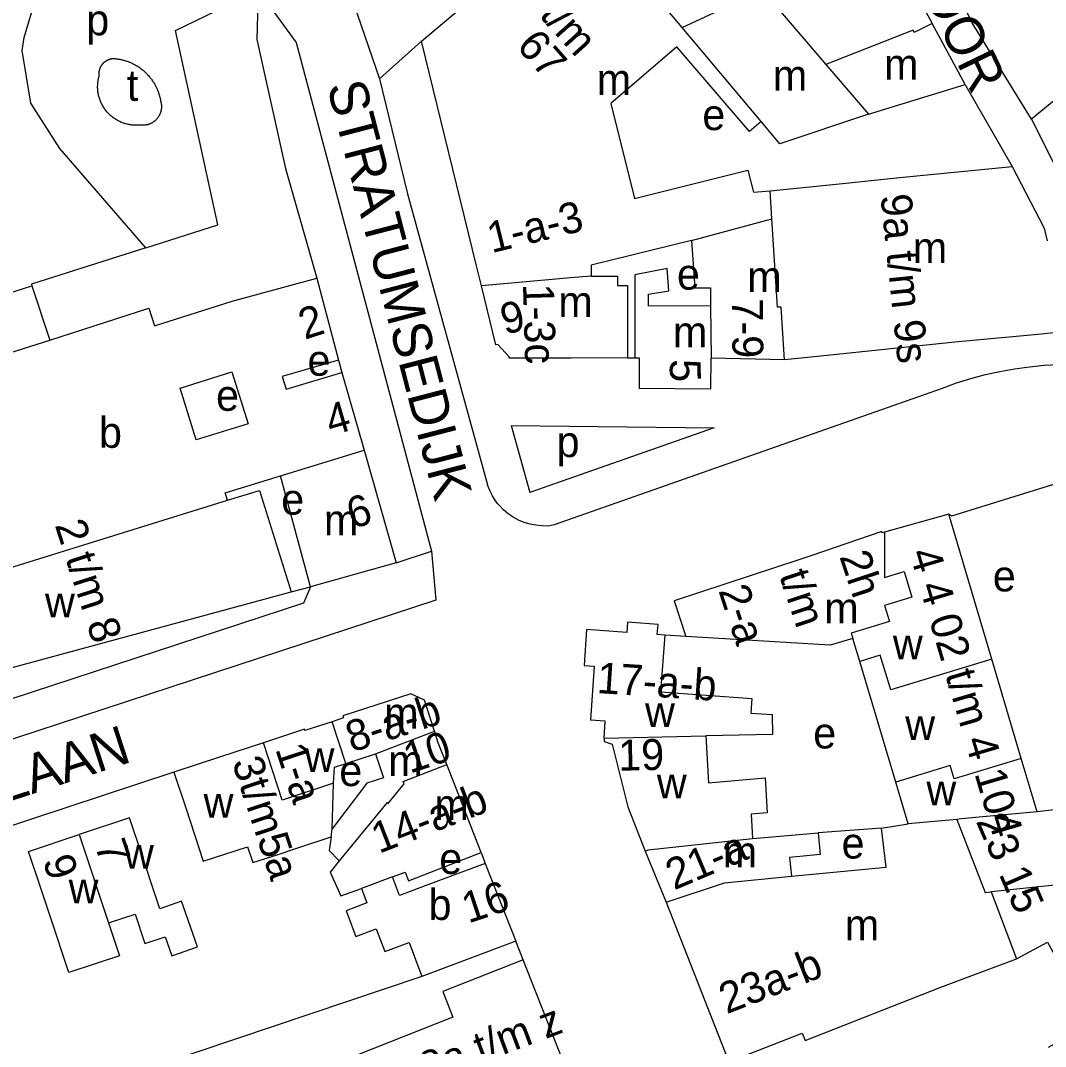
# Model space of a CAD drawing. Extents: x 160673 to 161924, y 382258 to 384145.
# Drawn here: x 161653.4 to 161785.9, y 382756.1 to 382888.8 of the extents above; entities that cross this region are included whole.
import ezdxf

# ---------------------------------------------------------------- set-up
doc = ezdxf.new("R2010")
doc.units = 0
for name, color, linetype in [('BLT_Basislijn', 7, 'Continuous'), ('BLT_Bebouwing', 7, 'Continuous'), ('BLT_Centroide', 7, 'Continuous'), ('BLT_Huisnummer', 7, 'Continuous'), ('BLT_Huisnummer_reeks', 7, 'Continuous'), ('BLT_Onderdoorgang_en_onderverdeling', 7, 'Continuous'), ('BLT_Onderverdeling_panden', 7, 'Continuous'), ('BLT_Straatnaam', 7, 'Continuous')]:
    doc.layers.add(name, color=color, linetype=linetype)

msp = doc.modelspace()

# ---------------------------------------------------------------- linework, layer by layer
at = {"layer": 'BLT_Basislijn'}
for p, q in [((161696.46, 382891.05), (161699.83, 382881.27)), ((161699.83, 382881.27), (161705.26, 382886.11)), ((161775.81, 382880.04), (161781.64, 382869.92)), ((161687.67, 382869.67), (161691.73, 382855.47)), ((161731.89, 382845.15), (161732.86, 382845.18)), ((161694.52, 382844.86), (161694.96, 382843.25)), ((161771.86, 382840.94), (161722.4, 382823.55)), ((161722.4, 382823.55), (161721.64, 382823.38)), ((161701.98, 382818.64), (161706.56, 382820.15)), ((161688.4, 382814.89), (161690.9, 382815.57)), ((161739.44, 382809.11), (161736.71, 382809.3)), ((161764.74, 382784.33), (161756.57, 382783.73)), ((161712.96, 382781.19), (161713.49, 382779.79)), ((161718.38, 382767.32), (161717.44, 382769.71))]:
    msp.add_line(p, q, dxfattribs=at)
for points in [[(161784.14, 382876.02), (161776.46, 382888.51), (161772.05, 382897.69), (161770.77, 382900), (161757.99, 382926.38), (161756.93, 382927.5), (161750.63, 382931.05)], [(161669.6, 382859.39), (161658.47, 382872.25), (161654.74, 382878.09), (161653.59, 382884.93), (161653.85, 382886.6), (161655.45, 382891.97), (161655.94, 382893.21), (161660.68, 382894.52), (161664.2, 382895.29), (161667.2, 382896.2), (161670.19, 382897.12), (161675.06, 382898.91), (161679.92, 382900.69)], [(161762.41, 382899.43), (161763.63, 382900), (161764.76, 382900.57), (161765.06, 382900), (161771.29, 382888.41)], [(161669.6, 382859.39), (161678.93, 382862.35), (161673.43, 382887.52), (161684.14, 382892.71)], [(161684.14, 382892.71), (161683.96, 382886.35), (161687.67, 382869.67)], [(161684.14, 382892.71), (161689.03, 382885.93), (161706.56, 382820.15)], [(161663.57, 382881.66), (161663.57, 382881.69), (161663.56, 382881.73), (161663.56, 382881.77), (161663.56, 382881.8), (161663.56, 382881.84), (161663.56, 382881.88), (161663.56, 382881.92), (161663.56, 382881.96), (161663.56, 382882), (161663.56, 382882.03), (161663.56, 382882.07), (161663.57, 382882.11), (161663.57, 382882.15), (161663.58, 382882.19), (161663.58, 382882.23), (161663.59, 382882.27), (161663.6, 382882.31), (161663.61, 382882.35), (161663.62, 382882.39), (161663.63, 382882.43), (161663.64, 382882.47), (161663.65, 382882.51), (161663.66, 382882.55), (161663.68, 382882.59), (161663.69, 382882.63), (161663.71, 382882.67), (161663.72, 382882.7), (161663.74, 382882.74), (161663.76, 382882.78), (161663.78, 382882.82), (161663.8, 382882.86), (161663.82, 382882.89), (161663.84, 382882.93), (161663.86, 382882.97), (161663.89, 382883), (161663.91, 382883.04), (161663.94, 382883.07), (161663.96, 382883.11), (161663.99, 382883.14), (161664.01, 382883.18), (161664.04, 382883.21), (161664.07, 382883.24), (161664.1, 382883.27), (161664.13, 382883.3), (161664.16, 382883.33), (161664.19, 382883.36), (161664.22, 382883.39), (161664.26, 382883.42), (161664.29, 382883.45), (161664.32, 382883.47), (161664.36, 382883.5), (161664.39, 382883.52), (161664.42, 382883.55), (161664.46, 382883.57), (161664.5, 382883.59), (161664.53, 382883.61), (161664.57, 382883.63), (161664.6, 382883.65), (161664.64, 382883.67), (161664.68, 382883.69), (161664.71, 382883.71), (161664.75, 382883.72), (161664.79, 382883.74), (161664.83, 382883.75), (161664.86, 382883.77), (161664.9, 382883.78), (161664.94, 382883.79), (161664.98, 382883.81), (161665.01, 382883.82), (161665.05, 382883.83), (161665.09, 382883.83), (161665.13, 382883.84), (161665.16, 382883.85), (161665.2, 382883.86), (161665.24, 382883.86), (161665.28, 382883.87), (161665.31, 382883.87), (161665.35, 382883.88), (161665.39, 382883.88)], [(161665.39, 382883.88), (161665.49, 382883.87), (161665.59, 382883.86), (161665.7, 382883.85), (161665.81, 382883.84), (161665.91, 382883.83), (161666.02, 382883.81), (161666.13, 382883.79), (161666.23, 382883.78), (161666.34, 382883.75), (161666.45, 382883.73), (161666.55, 382883.71), (161666.66, 382883.68), (161666.77, 382883.65), (161666.88, 382883.62), (161666.98, 382883.59), (161667.09, 382883.55), (161667.2, 382883.52), (161667.3, 382883.48), (161667.41, 382883.44), (161667.51, 382883.4), (161667.62, 382883.35), (161667.72, 382883.31), (161667.83, 382883.26), (161667.93, 382883.21), (161668.03, 382883.16), (161668.14, 382883.1), (161668.24, 382883.05), (161668.34, 382882.99), (161668.44, 382882.93), (161668.54, 382882.87), (161668.64, 382882.8), (161668.73, 382882.74), (161668.83, 382882.67), (161668.92, 382882.6), (161669.02, 382882.53), (161669.11, 382882.46), (161669.2, 382882.39), (161669.29, 382882.31), (161669.38, 382882.24), (161669.47, 382882.16), (161669.55, 382882.08), (161669.64, 382882), (161669.72, 382881.91), (161669.8, 382881.83), (161669.88, 382881.74), (161669.96, 382881.66), (161670.04, 382881.57), (161670.11, 382881.48), (161670.18, 382881.39), (161670.26, 382881.29), (161670.33, 382881.2), (161670.39, 382881.11), (161670.46, 382881.01), (161670.52, 382880.92), (161670.59, 382880.82), (161670.65, 382880.72), (161670.71, 382880.62), (161670.76, 382880.52), (161670.82, 382880.42), (161670.87, 382880.32), (161670.92, 382880.22), (161670.97, 382880.12), (161671.02, 382880.02), (161671.06, 382879.91), (161671.11, 382879.81), (161671.15, 382879.71), (161671.19, 382879.6), (161671.23, 382879.5), (161671.26, 382879.4), (161671.3, 382879.29), (161671.33, 382879.19), (161671.36, 382879.08), (161671.39, 382878.98), (161671.42, 382878.88), (161671.44, 382878.77), (161671.46, 382878.67), (161671.48, 382878.56), (161671.5, 382878.46), (161671.52, 382878.36)], [(161668.89, 382875.26), (161668.78, 382875.25), (161668.67, 382875.24), (161668.57, 382875.24), (161668.46, 382875.24), (161668.35, 382875.24), (161668.23, 382875.24), (161668.12, 382875.24), (161668.01, 382875.25), (161667.89, 382875.26), (161667.78, 382875.27), (161667.66, 382875.29), (161667.55, 382875.3), (161667.43, 382875.33), (161667.31, 382875.35), (161667.19, 382875.38), (161667.07, 382875.41), (161666.95, 382875.44), (161666.84, 382875.48), (161666.72, 382875.52), (161666.6, 382875.56), (161666.48, 382875.61), (161666.36, 382875.66), (161666.25, 382875.71), (161666.13, 382875.77), (161666.02, 382875.83), (161665.9, 382875.89), (161665.79, 382875.96), (161665.68, 382876.03), (161665.57, 382876.1), (161665.46, 382876.17), (161665.35, 382876.25), (161665.24, 382876.34), (161665.14, 382876.42), (161665.04, 382876.51), (161664.94, 382876.6), (161664.84, 382876.69), (161664.75, 382876.79), (161664.66, 382876.89), (161664.57, 382876.99), (161664.48, 382877.09), (161664.4, 382877.2), (161664.32, 382877.31), (161664.24, 382877.42), (161664.17, 382877.53), (161664.1, 382877.65), (161664.03, 382877.76), (161663.96, 382877.88), (161663.9, 382878), (161663.84, 382878.12), (161663.79, 382878.24), (161663.74, 382878.36), (161663.69, 382878.48), (161663.65, 382878.61), (161663.6, 382878.73), (161663.57, 382878.86), (161663.53, 382878.98), (161663.5, 382879.1), (161663.48, 382879.23), (161663.45, 382879.35), (161663.43, 382879.48), (161663.41, 382879.6), (161663.4, 382879.73), (161663.39, 382879.85), (161663.38, 382879.97), (161663.37, 382880.09), (161663.37, 382880.21), (161663.37, 382880.33), (161663.38, 382880.45), (161663.38, 382880.57), (161663.39, 382880.68), (161663.4, 382880.8), (161663.42, 382880.91), (161663.43, 382881.02), (161663.45, 382881.13), (161663.47, 382881.24), (161663.5, 382881.35), (161663.52, 382881.45), (161663.55, 382881.55), (161663.57, 382881.66)], [(161699.83, 382881.27), (161703.43, 382866.39), (161713.79, 382828.76)], [(161775.55, 382880.5), (161775.65, 382880.33), (161775.81, 382880.04)], [(161671.52, 382878.36), (161671.54, 382878.31), (161671.55, 382878.26), (161671.56, 382878.21), (161671.57, 382878.15), (161671.58, 382878.1), (161671.59, 382878.05), (161671.6, 382877.99), (161671.61, 382877.94), (161671.61, 382877.88), (161671.62, 382877.82), (161671.62, 382877.77), (161671.62, 382877.71), (161671.62, 382877.65), (161671.62, 382877.59), (161671.62, 382877.53), (161671.62, 382877.47), (161671.61, 382877.41), (161671.6, 382877.35), (161671.6, 382877.29), (161671.59, 382877.23), (161671.57, 382877.17), (161671.56, 382877.1), (161671.54, 382877.04), (161671.53, 382876.98), (161671.51, 382876.92), (161671.49, 382876.86), (161671.47, 382876.8), (161671.44, 382876.74), (161671.42, 382876.68), (161671.39, 382876.62), (161671.36, 382876.56), (161671.33, 382876.5), (161671.3, 382876.44), (161671.26, 382876.39), (161671.23, 382876.33), (161671.19, 382876.28), (161671.15, 382876.22), (161671.11, 382876.17), (161671.07, 382876.12), (161671.02, 382876.07), (161670.98, 382876.02), (161670.93, 382875.97), (161670.89, 382875.92), (161670.84, 382875.88), (161670.79, 382875.83), (161670.74, 382875.79), (161670.69, 382875.75), (161670.63, 382875.71), (161670.58, 382875.67), (161670.53, 382875.63), (161670.47, 382875.6), (161670.42, 382875.57), (161670.36, 382875.53), (161670.3, 382875.5), (161670.24, 382875.48), (161670.19, 382875.45), (161670.13, 382875.42), (161670.07, 382875.4), (161670.01, 382875.38), (161669.95, 382875.36), (161669.89, 382875.34), (161669.84, 382875.32), (161669.78, 382875.31), (161669.72, 382875.3), (161669.66, 382875.28), (161669.6, 382875.27), (161669.54, 382875.26), (161669.49, 382875.26), (161669.43, 382875.25), (161669.37, 382875.25), (161669.32, 382875.24), (161669.26, 382875.24), (161669.2, 382875.24), (161669.15, 382875.24), (161669.1, 382875.24), (161669.04, 382875.25), (161668.99, 382875.25), (161668.94, 382875.26), (161668.89, 382875.26)], [(161669.6, 382859.39), (161654.81, 382854.69), (161654.88, 382854.49)], [(161644.34, 382843.41), (161642.05, 382850.53), (161641.85, 382851.77), (161641.96, 382853.02), (161642.37, 382854.21), (161643.08, 382855.25), (161644.05, 382856.05), (161645.15, 382856.66), (161646.38, 382856.92), (161647.64, 382856.88), (161649.02, 382856.46), (161650.05, 382855.84), (161650.9, 382854.98), (161651.64, 382853.46), (161654.88, 382854.49)], [(161654.88, 382854.49), (161657.17, 382847.46)], [(161793.56, 382844.1), (161791.63, 382844.24), (161789.68, 382844.29), (161787.74, 382844.27), (161785.8, 382844.16), (161783.87, 382843.98), (161781.95, 382843.71), (161780.04, 382843.37), (161778.14, 382842.95), (161776.26, 382842.45), (161774.41, 382841.88), (161772.58, 382841.22), (161771.86, 382840.94)], [(161716.87, 382836.41), (161719.26, 382827.74)], [(161716.87, 382836.41), (161743.1, 382836.13)], [(161743.1, 382836.13), (161719.26, 382827.74)], [(161715.14, 382826.3), (161714.84, 382826.67), (161714.42, 382827.33), (161714.07, 382828.03), (161713.79, 382828.76)], [(161773.44, 382824.94), (161773.84, 382824.74), (161787.59, 382828.98)], [(161721.64, 382823.38), (161720.84, 382823.44), (161720.06, 382823.51), (161719.29, 382823.66), (161718.54, 382823.88), (161717.81, 382824.18), (161717.12, 382824.55), (161716.48, 382824.99), (161715.87, 382825.49), (161715.33, 382826.05), (161715.14, 382826.3)], [(161706.56, 382820.15), (161707.11, 382813.82), (161604.11, 382780.01)], [(161690.9, 382815.57), (161690, 382813.46), (161638.43, 382796.53)], [(161673.24, 382791.58), (161599.67, 382767.3), (161594.58, 382765.48), (161592.95, 382764.43), (161588.72, 382761.07), (161582.73, 382756.8), (161576.92, 382752.34), (161575.39, 382751.38), (161572.83, 382749.04)], [(161705.29, 382765.14), (161671.57, 382753.82), (161672.26, 382751.88), (161666.99, 382750.02), (161666.19, 382749.74), (161666.83, 382747.94), (161647.7, 382741.2)]]:
    msp.add_lwpolyline(points, dxfattribs=at)
at = {"layer": 'BLT_Bebouwing'}
for p, q in [((161809.67, 382897.12), (161784.14, 382876.02)), ((161749.33, 382892.73), (161757.56, 382883.09)), ((161775.55, 382880.5), (161771.29, 382888.41)), ((161763.07, 382876.66), (161775.55, 382880.5)), ((161767.1, 382868.47), (161781.64, 382869.92)), ((161750.34, 382866.78), (161758.44, 382867.6)), ((161758.44, 382867.6), (161767.1, 382868.47)), ((161750.57, 382863.13), (161750.34, 382866.78)), ((161740.19, 382860.32), (161750.57, 382863.13)), ((161713.01, 382854.49), (161712.38, 382857.06)), ((161691.73, 382855.47), (161694.52, 382844.86)), ((161784.52, 382848.14), (161774.64, 382847.22)), ((161787.52, 382848.44), (161784.52, 382848.14)), ((161724.63, 382845.14), (161717.66, 382845.13)), ((161731.89, 382845.15), (161724.63, 382845.14)), ((161752.2, 382844.92), (161742.7, 382845.12)), ((161694.52, 382844.86), (161687.25, 382842.74)), ((161694.96, 382843.25), (161697.83, 382833.21)), ((161697.83, 382833.21), (161701.98, 382818.64)), ((161690.9, 382815.57), (161687, 382829.89)), ((161773.44, 382824.94), (161765.15, 382822.62)), ((161779.01, 382806.18), (161773.44, 382824.94)), ((161701.98, 382818.64), (161690.9, 382815.57)), ((161754.32, 382819.13), (161737.91, 382813.73)), ((161755.62, 382819.57), (161754.32, 382819.13)), ((161635.19, 382800.49), (161688.4, 382814.89)), ((161737.91, 382813.73), (161739.44, 382809.11)), ((161761.93, 382805.9), (161761.04, 382808.89)), ((161766.59, 382790.3), (161761.93, 382805.9)), ((161782.81, 382793.37), (161779.01, 382806.18)), ((161688.06, 382796.45), (161684.81, 382795.38)), ((161684.81, 382795.38), (161679.14, 382793.52)), ((161679.14, 382793.52), (161673.24, 382791.58)), ((161784.86, 382786.47), (161782.81, 382793.37)), ((161712.96, 382781.19), (161708.53, 382792.58)), ((161768.2, 382784.89), (161766.59, 382790.3)), ((161764.74, 382784.33), (161768.2, 382784.89)), ((161734.2, 382781.37), (161736.91, 382774.75)), ((161701.51, 382778.05), (161703.14, 382778.65)), ((161713.49, 382779.79), (161717.44, 382769.71)), ((161736.91, 382774.75), (161745, 382754.12)), ((161717.44, 382769.71), (161705.29, 382765.14)), ((161724.12, 382752.78), (161718.38, 382767.32))]:
    msp.add_line(p, q, dxfattribs=at)
for points in [[(161712.38, 382857.06), (161705.26, 382886.11), (161725.82, 382903.46)], [(161771.29, 382888.41), (161768.96, 382887.22), (161768.84, 382887.53), (161757.56, 382883.09)], [(161738.29, 382885.39), (161729.72, 382878.05), (161732.78, 382865.78)], [(161749.17, 382875.71), (161747.67, 382874.42), (161738.29, 382885.39)], [(161763.07, 382876.66), (161751.61, 382872.86), (161749.17, 382875.71)], [(161784.14, 382876.02), (161789.67, 382865.07), (161791.04, 382860.71)], [(161732.78, 382865.78), (161747.47, 382869.44), (161748.19, 382866.58), (161750.34, 382866.78)], [(161781.64, 382869.92), (161785.8, 382861.92), (161786.16, 382860.28)], [(161740.19, 382860.32), (161727.19, 382857.14), (161727.19, 382855.74)], [(161740.19, 382860.32), (161740.62, 382854.2), (161742.61, 382854.2), (161742.63, 382851.88)], [(161727.19, 382855.74), (161730.58, 382855.74), (161730.58, 382854.51), (161731.89, 382854.51), (161731.89, 382850.15), (161731.89, 382845.15)], [(161742.63, 382851.88), (161734.63, 382851.87), (161734.63, 382853.4), (161737.26, 382853.85), (161737.04, 382856.74), (161732.85, 382855.91), (161732.85, 382850.11), (161732.86, 382845.18)], [(161670.73, 382849.29), (161680.77, 382852.48), (161691.73, 382855.47)], [(161717.66, 382845.13), (161716.61, 382845.13), (161716.61, 382845.3), (161715.11, 382846.91), (161714.88, 382846.86), (161713.01, 382854.49)], [(161657.17, 382847.46), (161669.99, 382851.6), (161670.73, 382849.29)], [(161644.34, 382843.41), (161657.17, 382847.46)], [(161774.64, 382847.22), (161755.22, 382845.22), (161752.2, 382844.92)], [(161732.86, 382845.18), (161733.41, 382845.17), (161733.41, 382841.24), (161742.66, 382841.14), (161742.7, 382845.12)], [(161687.25, 382842.74), (161687.73, 382841.12), (161694.96, 382843.25)], [(161680.18, 382826.76), (161679.88, 382827.71), (161687, 382829.89)], [(161680.18, 382826.76), (161684.3, 382828.03), (161688.4, 382814.89)], [(161765.15, 382822.62), (161764.84, 382822.53), (161764.78, 382822.71), (161755.62, 382819.57)], [(161736.71, 382809.3), (161735.74, 382809.37), (161735.84, 382810.69), (161731.89, 382810.98), (161731.79, 382809.66), (161726.61, 382810.04)], [(161726.61, 382810.04), (161726.27, 382805.37), (161727.6, 382805.27), (161727.12, 382798.29)], [(161736.71, 382809.3), (161736.17, 382801.98), (161747.98, 382801.12), (161747.84, 382799.23), (161750.61, 382799.03), (161750.64, 382796.44), (161742.02, 382796.29)], [(161761.04, 382808.89), (161758.1, 382808.01), (161739.44, 382809.11)], [(161703.86, 382801.71), (161695.1, 382798.86), (161695.18, 382798.59), (161693.7, 382798.11)], [(161706.94, 382796.89), (161705.62, 382800.91), (161703.86, 382801.71)], [(161693.7, 382798.11), (161690.18, 382796.95), (161690.13, 382797.13), (161688.06, 382796.45)], [(161728.89, 382795.99), (161728.99, 382798.18), (161727.12, 382798.29)], [(161708.53, 382792.58), (161707.43, 382795.39), (161706.94, 382796.89)], [(161728.89, 382795.99), (161728.87, 382795.53), (161729.92, 382795.22), (161731.94, 382787.1)], [(161742.02, 382796.29), (161742.36, 382790.22), (161749.68, 382790.86), (161749.94, 382786.32), (161747.87, 382786.14), (161748.04, 382783.01)], [(161699.31, 382793.96), (161700.33, 382790.85), (161698.18, 382790.14), (161693.69, 382784.25)], [(161695.48, 382792.7), (161699.31, 382793.96)], [(161693.88, 382790.18), (161694.02, 382792.22), (161695.48, 382792.7)], [(161673.24, 382791.58), (161674.8, 382786.83), (161677.03, 382780.06), (161682.76, 382781.94)], [(161693.69, 382784.25), (161693.88, 382790.13), (161693.88, 382790.18)], [(161797.5, 382787.92), (161784.86, 382786.47)], [(161731.94, 382787.1), (161734.2, 382781.37)], [(161671.42, 382773.92), (161670.99, 382775.21), (161669.09, 382780.93), (161667.51, 382785.67), (161660.98, 382783.5)], [(161753.1, 382778.12), (161765.34, 382779.31), (161764.74, 382784.33)], [(161664.78, 382772.08), (161666.2, 382767.84), (161659.66, 382765.66), (161657.27, 382772.81), (161656.02, 382776.58), (161654.44, 382781.32), (161660.98, 382783.5)], [(161689.28, 382781.79), (161693.56, 382783.2)], [(161693.56, 382783.2), (161693.33, 382781.44), (161694.62, 382780.11)], [(161748.04, 382783.01), (161750.14, 382783.19), (161756.57, 382783.73)], [(161756.57, 382783.73), (161756.82, 382780.94), (161752.84, 382780.53), (161753.1, 382778.12)], [(161682.76, 382781.94), (161683.45, 382779.88)], [(161683.45, 382779.88), (161686.57, 382780.9), (161689.28, 382781.79)], [(161694.62, 382780.11), (161693.43, 382778.66), (161694.81, 382775.59), (161697.49, 382776.55)], [(161703.14, 382778.65), (161703.58, 382777.54), (161708.3, 382779.38), (161712.96, 382781.19)], [(161713.49, 382779.79), (161708.98, 382778.11), (161706.41, 382777.15), (161702.4, 382775.65), (161701.51, 382778.05)], [(161802.43, 382778.58), (161778.92, 382776.11)], [(161697.49, 382776.55), (161698.2, 382774.67), (161695.5, 382773.66), (161696.74, 382770.35), (161699.4, 382771.34), (161700.5, 382768.39), (161703.64, 382769.56), (161705.29, 382765.14)], [(161778.92, 382776.11), (161782.19, 382767.44)], [(161664.78, 382772.08), (161668.23, 382773.23), (161669.49, 382769.43), (161672.1, 382770.29), (161672.96, 382767.83), (161676.28, 382768.99), (161674.21, 382774.9), (161671.42, 382773.92)], [(161782.19, 382767.44), (161786.19, 382769.61), (161792, 382759.11), (161786.31, 382755.99)], [(161718.38, 382767.32), (161708, 382763.22), (161709.29, 382759.89), (161674.33, 382746.06), (161674.84, 382744.75), (161673.54, 382741.71), (161680.53, 382738.61), (161681.59, 382736.05), (161724.12, 382752.78)]]:
    msp.add_lwpolyline(points, dxfattribs=at)
msp.add_lwpolyline([(161674.03, 382841.24), (161680.72, 382843.34), (161682.82, 382836.65), (161676.12, 382834.55)], close=True, dxfattribs=at)
at = {"layer": 'BLT_Onderdoorgang_en_onderverdeling'}
for points in [[(161779.01, 382806.18), (161765.96, 382802.21), (161764.59, 382806.71), (161761.93, 382805.9)], [(161782.81, 382793.37), (161774.15, 382790.72), (161773.62, 382792.44), (161766.59, 382790.3)]]:
    msp.add_lwpolyline(points, dxfattribs=at)
at = {"layer": 'BLT_Onderverdeling_panden'}
for p, q in [((161738.95, 382887.9), (161725.82, 382903.46)), ((161738.95, 382887.9), (161749.33, 382892.73)), ((161749.17, 382875.71), (161738.95, 382887.9)), ((161757.56, 382883.09), (161763.07, 382876.66)), ((161727.19, 382855.74), (161724.53, 382855.5)), ((161717.38, 382854.88), (161713.01, 382854.49)), ((161724.53, 382855.5), (161717.38, 382854.88)), ((161742.63, 382851.88), (161742.7, 382845.12)), ((161687, 382829.89), (161697.83, 382833.21)), ((161695.48, 382792.7), (161693.7, 382798.11)), ((161699.31, 382793.96), (161706.94, 382796.89)), ((161728.89, 382795.99), (161742.02, 382796.29)), ((161700.88, 382787.49), (161703.03, 382790.06)), ((161774.5, 382785.47), (161768.2, 382784.89)), ((161693.56, 382783.2), (161693.69, 382784.25)), ((161660.98, 382783.5), (161664.78, 382772.08)), ((161701.51, 382778.05), (161697.49, 382776.55)), ((161772.4, 382763.76), (161782.19, 382767.44))]:
    msp.add_line(p, q, dxfattribs=at)
for points in [[(161752.2, 382844.92), (161751.76, 382851.74), (161751.31, 382851.71), (161750.57, 382863.13)], [(161630.96, 382813.95), (161637.06, 382815.91), (161637.84, 382813.63), (161680.18, 382826.76)], [(161765.15, 382822.62), (161765.13, 382816.76), (161767.67, 382817.53), (161768.68, 382814.2), (161765.14, 382813.13), (161765.77, 382811.06), (161760.84, 382809.57), (161761.04, 382808.89)], [(161693.88, 382790.18), (161687.24, 382787.98), (161684.81, 382795.38)], [(161703.03, 382790.06), (161702.9, 382790.39), (161708.53, 382792.58)], [(161700.88, 382787.49), (161700.82, 382787.65), (161694.62, 382780.11)], [(161784.86, 382786.47), (161775.04, 382785.53), (161774.5, 382785.47)], [(161774.5, 382785.47), (161778.14, 382776.02), (161778.92, 382776.11)], [(161734.2, 382781.37), (161734.56, 382781.54), (161748.04, 382783.01)], [(161736.91, 382774.75), (161744.44, 382777.25), (161753.1, 382778.12)], [(161745, 382754.12), (161754.5, 382757.83), (161754.87, 382756.87), (161772.4, 382763.76)]]:
    msp.add_lwpolyline(points, dxfattribs=at)

# ---------------------------------------------------------------- texts
at = {"layer": 'BLT_Centroide'}
for s, p in [('p', (161661.89, 382886.88)), ('m', (161765.07, 382881.14)), ('t', (161667.14, 382878.4)), ('m', (161727.91, 382879.17)), ('m', (161750.68, 382879.7)), ('e', (161741.57, 382874.62)), ('m', (161768.78, 382857.41)), ('e', (161738.29, 382853.99)), ('m', (161747.38, 382853.66)), ('m', (161722.95, 382850.44)), ('m', (161737.77, 382846.53)), ('e', (161690.51, 382842.85)), ('e', (161678.68, 382838.31)), ('b', (161663.54, 382833.53)), ('p', (161722.72, 382832.33)), ('e', (161687.11, 382824.88)), ('m', (161692.64, 382822.2)), ('e', (161779.14, 382814.96)), ('w', (161656.56, 382811.6)), ('m', (161757.34, 382810.81)), ('w', (161766.21, 382806.17)), ('m', (161700.42, 382797.22)), ('w', (161734.16, 382797.41)), ('w', (161767.81, 382795.73)), ('e', (161755.91, 382794.65)), ('w', (161690.14, 382791.61)), ('m', (161700.95, 382791.08)), ('e', (161694.62, 382789.78)), ('w', (161735.69, 382788.19)), ('w', (161770.55, 382787.3)), ('w', (161677.07, 382785.68)), ('m', (161706.92, 382785.39)), ('e', (161759.58, 382780.41)), ('w', (161666.78, 382779.09)), ('e', (161707.55, 382778.42)), ('m', (161744.2, 382779.28)), ('w', (161659.61, 382774.62)), ('b', (161706.16, 382772.47)), ('m', (161759.99, 382769.84))]:
    msp.add_text(s, height=4, dxfattribs=at).set_placement(p)
at = {"layer": 'BLT_Huisnummer'}
for s, rotation, p in [('5', 270.5638, (161737.36, 382844.99)), ('6', 16.3476, (161696.29, 382823.02)), ('10', 18.2137, (161703.74, 382791.38)), ('19', 1.3474, (161730.73, 382791.76)), ('7', 288.4139, (161662.96, 382782.14)), ('9', 288.4132, (161656.23, 382780.15)), ('16', 18.5451, (161711.3, 382771.99))]:
    msp.add_text(s, height=4, rotation=rotation, dxfattribs=at).set_placement(p)
at = {"layer": 'BLT_Huisnummer_reeks'}
for s, rotation, p in [('t/m', 311.7795, (161720.35, 382889.44)), ('67', 311.2733, (161717.41, 382885.42)), ('9a t/m 9s', 275.9228, (161764.61, 382866.18)), ('1-a-3', 13.7972, (161714.32, 382858.69)), ('1-3c', 271.6209, (161718.37, 382854.72)), ('2', 18.021, (161690.15, 382847.49)), ('9', 13.7922, (161716.03, 382848.13)), ('7-9', 270.5529, (161745.4, 382852.83)), ('4', 16.348, (161693.53, 382835.05)), ('2 t/m 8', 287.8329, (161657.81, 382823.55)), ('2h', 288.3676, (161759.27, 382819.49)), ('4 4 02 t/m 4 104', 286.4297, (161768.33, 382819.95)), ('t/m', 288.3676, (161751.48, 382817.05)), ('2-a', 288.3676, (161743.62, 382815.08)), ('17-a-b', 356.2702, (161727.86, 382801.82)), ('8-a-b', 18.0062, (161696.25, 382794.11)), ('1-a', 288.1914, (161686.32, 382794.59)), ('3t/m5a', 288.201, (161680.71, 382792.89)), ('14-a-b', 21.2375, (161699.75, 382781.01)), ('23 15', 293.4841, (161776.91, 382785.24)), ('21-a', 22.9267, (161737.91, 382776.28)), ('23a-b', 21.3562, (161744.71, 382760.26)), ('18a t/m z', 20.4703, (161703.19, 382750.3))]:
    msp.add_text(s, height=4, rotation=rotation, dxfattribs=at).set_placement(p)
at = {"layer": 'BLT_Straatnaam'}
for s, height, rotation, p in [('ONDERDOOR', 5, 295.9019, (161757.2, 382918.81)), ('STRATUMSEDIJK', 4.9999, 284.5689, (161693, 382880.34)), ('BILDERDIJKLAAN', 5, 17.9765, (161614.57, 382775.65))]:
    msp.add_text(s, height=height, rotation=rotation, dxfattribs=at).set_placement(p)

doc.saveas('drawing.dxf')
